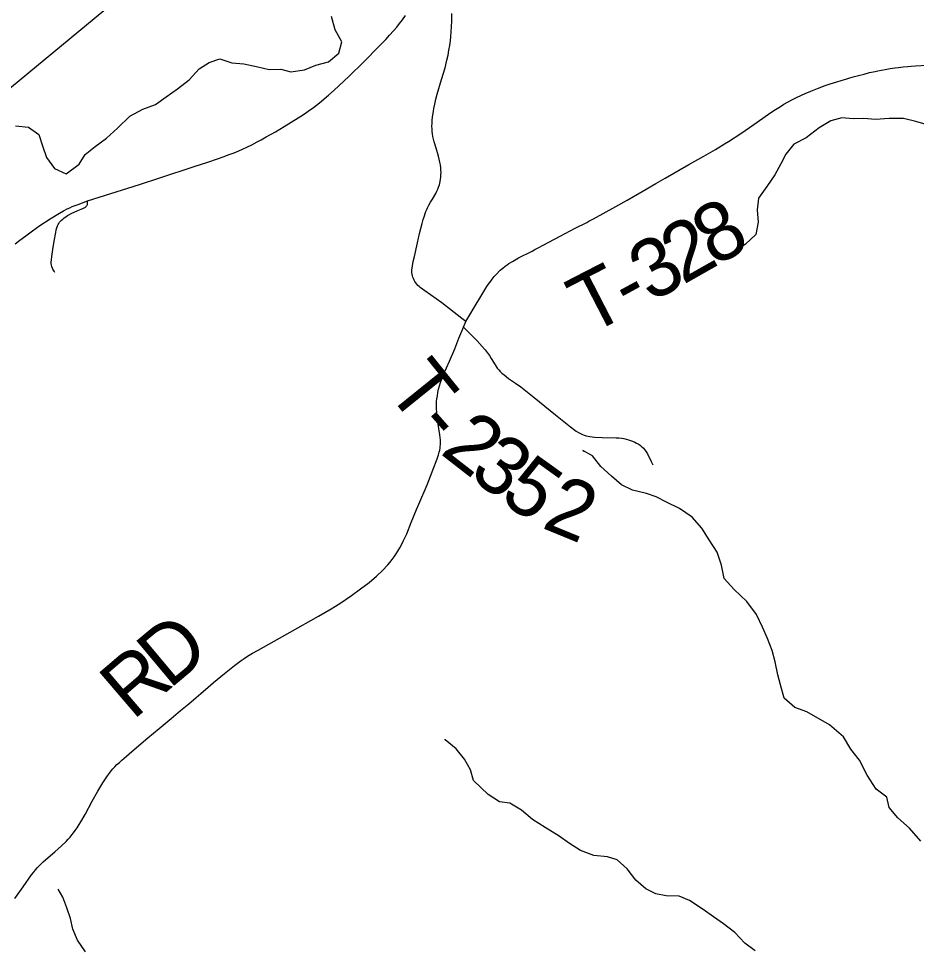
# Model space of a CAD drawing. Extents: x 0 to 34, y 0 to 22.
# Drawn here: x 26.124 to 26.994, y 17.712 to 18.613 of the extents above; entities that cross this region are included whole.
import ezdxf

# ---------------------------------------------------------------- set-up
doc = ezdxf.new("R2010")
doc.units = 0
for name, color, linetype in [('GM_X_Minor_River', 7, 'Continuous'), ('GM_X_Rail_Line', 7, 'Continuous'), ('GM_X_State_Route', 7, 'Continuous'), ('GM_X_Township_Road', 7, 'Continuous'), ('GM_X_Township_Road_Text', 7, 'Continuous')]:
    doc.layers.add(name, color=color, linetype=linetype)

msp = doc.modelspace()

# ---------------------------------------------------------------- linework, layer by layer
at = {"layer": 'GM_X_Minor_River'}
for points in [[(26.1706, 18.46225), (26.18299, 18.47148), (26.18896, 18.48101), (26.19872, 18.48869), (26.20962, 18.49676), (26.22012, 18.50634), (26.23211, 18.51821), (26.24491, 18.52479), (26.25696, 18.52946), (26.26748, 18.53677), (26.27838, 18.54446), (26.28964, 18.55329), (26.29938, 18.564), (26.30915, 18.57017), (26.31933, 18.57368), (26.33108, 18.56964), (26.34243, 18.56862), (26.35606, 18.56573), (26.36705, 18.5632), (26.37838, 18.56369), (26.38823, 18.56115), (26.40145, 18.5628), (26.41237, 18.56746), (26.42444, 18.57062), (26.43458, 18.57906), (26.4375, 18.59008), (26.43098, 18.60175), (26.42746, 18.6146)], [(27.00561, 18.50929), (26.9931, 18.51295), (26.98136, 18.51585), (26.96737, 18.51571), (26.95415, 18.51481), (26.9428, 18.51583), (26.9326, 18.51534), (26.92162, 18.51636), (26.91107, 18.5136), (26.89979, 18.50666), (26.88702, 18.49705), (26.87497, 18.49087), (26.8675, 18.48131), (26.86267, 18.47179), (26.85671, 18.46112), (26.84887, 18.45005), (26.84103, 18.4386), (26.83962, 18.42722), (26.84048, 18.41549), (26.83831, 18.40334), (26.82819, 18.39414), (26.81842, 18.38722), (26.81994, 18.3861)], [(26.12143, 18.50872), (26.13392, 18.50733), (26.14419, 18.50024), (26.14769, 18.48929), (26.15156, 18.47797), (26.15922, 18.46744), (26.1706, 18.46225)], [(26.99804, 17.81589), (26.98697, 17.82828), (26.97591, 17.83839), (26.96751, 17.84853), (26.96516, 17.85836), (26.95488, 17.8662), (26.94607, 17.87975), (26.93876, 17.89445), (26.93035, 17.90497), (26.92306, 17.91701), (26.90973, 17.92862), (26.8877, 17.94127), (26.87595, 17.94531), (26.86566, 17.9543), (26.86215, 17.96714), (26.85979, 17.97697), (26.85704, 17.98944), (26.8543, 18.0004), (26.84966, 18.0121), (26.84465, 18.02303), (26.83887, 18.03547), (26.82969, 18.04788), (26.81749, 18.0595), (26.80757, 18.07038), (26.80519, 18.08323), (26.80092, 18.09569), (26.79326, 18.10773), (26.78598, 18.11902), (26.77681, 18.12954), (26.76426, 18.13812), (26.75174, 18.14405), (26.74186, 18.14925), (26.73238, 18.15256), (26.71875, 18.15582), (26.70812, 18.16102), (26.6986, 18.16925), (26.68831, 18.17862), (26.68028, 18.18914), (26.67078, 18.19434), (26.67193, 18.19322)], [(26.83755, 17.70964), (26.82765, 17.71711), (26.81812, 17.72724), (26.80708, 17.73584), (26.79719, 17.74255), (26.7873, 17.74965), (26.774, 17.75823), (26.76413, 17.76266), (26.75165, 17.76291), (26.74143, 17.7647), (26.73194, 17.76953), (26.72203, 17.77814), (26.71362, 17.78903), (26.7041, 17.79765), (26.69462, 17.80058), (26.68138, 17.80196), (26.66848, 17.80675), (26.65784, 17.81345), (26.64795, 17.82055), (26.63427, 17.82912), (26.62211, 17.83695), (26.61144, 17.84593), (26.60004, 17.85263), (26.5902, 17.85404), (26.57918, 17.86112), (26.56507, 17.87461), (26.56196, 17.88481), (26.5562, 17.89536), (26.54818, 17.90512), (26.53751, 17.91411), (26.53751, 17.91448)], [(26.18926, 17.70852), (26.1816, 17.71981), (26.17697, 17.73075), (26.17461, 17.74095), (26.17112, 17.75114), (26.16725, 17.76171), (26.16265, 17.76924)]]:
    msp.add_lwpolyline(points, dxfattribs=at)
at = {"layer": 'GM_X_Rail_Line'}
msp.add_lwpolyline([(27.31815, 19.07874), (26.87194, 18.96304), (26.63643, 18.90218), (26.59839, 18.89255), (26.55991, 18.88003), (26.5181, 18.86299), (26.49385, 18.84892), (26.46587, 18.83157), (26.32991, 18.7221), (25.62545, 18.13949), (25.57168, 18.09086), (25.53163, 18.0529), (25.48854, 18.00437), (25.44769, 17.95909), (25.41457, 17.91805), (25.38062, 17.87119), (24.86025, 17.12657), (24.35774, 16.41254), (24.32043, 16.36582), (24.27944, 16.32479), (24.2417, 16.29196), (23.98974, 16.09826), (23.66779, 15.84317), (23.51667, 15.72346)], dxfattribs=at)
at = {"layer": 'GM_X_State_Route'}
msp.add_lwpolyline([(26.12118, 18.39433), (26.12578, 18.39802), (26.13137, 18.4023), (26.13786, 18.40715), (26.14516, 18.41221), (26.15503, 18.41862), (26.16407, 18.424), (26.16797, 18.42624), (26.17164, 18.42818), (26.17402, 18.42932), (26.17648, 18.43047), (26.17923, 18.43162), (26.18201, 18.43267), (26.19123, 18.43594), (26.20239, 18.4395), (26.24165, 18.45202), (26.26119, 18.4583), (26.29436, 18.46919), (26.3076, 18.47359), (26.31699, 18.47675), (26.32253, 18.47869), (26.32846, 18.48085), (26.3332, 18.48264), (26.33758, 18.48442), (26.34122, 18.48602), (26.34547, 18.48806), (26.35017, 18.49037), (26.35534, 18.49305), (26.35947, 18.49528), (26.36406, 18.49789), (26.3731, 18.50303), (26.38148, 18.50796), (26.39504, 18.51636), (26.40027, 18.51976), (26.40492, 18.52288), (26.40997, 18.52652), (26.41592, 18.53105), (26.42453, 18.53825), (26.43012, 18.5432), (26.44414, 18.55644), (26.45876, 18.5708), (26.47354, 18.58588), (26.48004, 18.59246), (26.48371, 18.59642), (26.48753, 18.60077), (26.49056, 18.60438), (26.49346, 18.60798), (26.49617, 18.61153), (26.499, 18.6155)], dxfattribs=at)
at = {"layer": 'GM_X_Township_Road'}
msp.add_line((26.55534, 18.3137), (26.55764, 18.31909), dxfattribs=at)
for points in [[(26.55764, 18.31909), (26.5538, 18.32212), (26.53415, 18.3372), (26.51774, 18.34892), (26.51333, 18.35207), (26.51222, 18.35309), (26.51111, 18.35416), (26.51006, 18.35532), (26.50901, 18.35663), (26.50814, 18.35795), (26.50737, 18.35934), (26.5067, 18.36087), (26.50626, 18.36205), (26.50589, 18.36334), (26.50556, 18.36493), (26.50539, 18.36655), (26.50535, 18.36781), (26.50539, 18.36914), (26.50556, 18.37098), (26.50583, 18.37295), (26.50669, 18.37745), (26.50773, 18.38217), (26.51078, 18.39545), (26.51271, 18.40457), (26.51515, 18.41423), (26.5162, 18.41783), (26.51735, 18.42141), (26.51818, 18.42375), (26.51896, 18.42584), (26.5197, 18.42765), (26.5204, 18.42913), (26.52106, 18.43049), (26.52177, 18.43179), (26.52332, 18.43464), (26.52518, 18.43777), (26.52833, 18.44306), (26.52952, 18.44537), (26.53045, 18.44743), (26.53121, 18.44936), (26.53189, 18.45141), (26.53236, 18.4531), (26.53276, 18.45492), (26.5331, 18.45712), (26.53333, 18.45912), (26.53347, 18.46123), (26.53351, 18.46336), (26.53343, 18.46584), (26.53324, 18.46818), (26.53289, 18.47085), (26.53243, 18.47355), (26.53182, 18.47644), (26.53105, 18.47946), (26.52872, 18.48704), (26.52689, 18.49325), (26.52567, 18.49841), (26.52523, 18.501), (26.52496, 18.50336), (26.5248, 18.50591), (26.52477, 18.50834), (26.5248, 18.51109), (26.52498, 18.51394), (26.52529, 18.51733), (26.5258, 18.52071), (26.5262, 18.52305), (26.52664, 18.52555), (26.52752, 18.52982), (26.52857, 18.53468), (26.52981, 18.53942), (26.53395, 18.5536), (26.53736, 18.56474), (26.53929, 18.57245), (26.54031, 18.57728), (26.54121, 18.58204), (26.54193, 18.58642), (26.5426, 18.5911), (26.5431, 18.59537), (26.54346, 18.59966), (26.54376, 18.6049), (26.54393, 18.61001), (26.54409, 18.61764)], [(26.55764, 18.31909), (26.56141, 18.32578), (26.56547, 18.3329), (26.57291, 18.34503), (26.57781, 18.35302), (26.57912, 18.35506), (26.58161, 18.35839), (26.58304, 18.36019), (26.58509, 18.36261), (26.587, 18.36484), (26.59087, 18.36875), (26.59335, 18.37091), (26.59553, 18.37268), (26.5975, 18.37412), (26.59906, 18.37527), (26.60256, 18.37746), (26.60848, 18.38069), (26.62166, 18.38739), (26.62438, 18.3888), (26.62765, 18.39046), (26.63246, 18.39296), (26.64872, 18.40171), (26.66351, 18.40956), (26.67456, 18.41521), (26.67675, 18.41635), (26.68114, 18.41861), (26.70282, 18.43066), (26.71359, 18.43675), (26.72813, 18.44499), (26.74156, 18.45274), (26.75067, 18.45802), (26.77344, 18.47125), (26.78788, 18.47934), (26.79913, 18.48578), (26.80815, 18.4912), (26.81185, 18.49349), (26.82378, 18.50126), (26.83649, 18.5101), (26.85068, 18.52007), (26.85591, 18.52365), (26.86207, 18.52751), (26.86548, 18.52965), (26.8695, 18.53194), (26.87386, 18.53429), (26.87772, 18.53623), (26.88241, 18.53844), (26.88614, 18.5401), (26.8917, 18.54243), (26.89817, 18.54501), (26.90547, 18.54769), (26.91044, 18.54931), (26.9167, 18.55139), (26.92107, 18.5527), (26.92549, 18.55406), (26.92938, 18.55516), (26.93375, 18.55636), (26.93774, 18.55743), (26.94313, 18.55884), (26.9485, 18.56023), (26.95391, 18.56139), (26.95632, 18.56197), (26.95989, 18.56273), (26.96358, 18.56343), (26.96848, 18.56421), (26.97292, 18.56487), (26.97639, 18.56527), (26.9811, 18.56581), (26.98563, 18.56618), (26.98871, 18.56642), (26.99304, 18.56675), (27.00415, 18.56762)], [(26.15969, 18.36654), (26.15879, 18.36809), (26.15777, 18.36998), (26.15707, 18.37143), (26.15666, 18.37252), (26.15635, 18.37375), (26.15615, 18.37521), (26.15615, 18.3768), (26.15629, 18.37877), (26.15664, 18.38205), (26.15768, 18.38904), (26.15897, 18.39684), (26.16046, 18.40541), (26.161, 18.40798), (26.1615, 18.4098), (26.16186, 18.41094), (26.16227, 18.41197), (26.16278, 18.41304), (26.16351, 18.41422), (26.16424, 18.41526), (26.16507, 18.4163), (26.16601, 18.41731), (26.16725, 18.41842), (26.16856, 18.41953), (26.17018, 18.42069), (26.17193, 18.42179), (26.17387, 18.42295), (26.17595, 18.42405), (26.1783, 18.42513), (26.18188, 18.42668), (26.18521, 18.42804), (26.18738, 18.4289), (26.18854, 18.42948), (26.18923, 18.42997), (26.18987, 18.43052), (26.19034, 18.43112), (26.19075, 18.43173), (26.19104, 18.43247), (26.1912, 18.43318), (26.19129, 18.43387), (26.19129, 18.43461), (26.19123, 18.43594)], [(26.12086, 17.76016), (26.12892, 17.7716), (26.13708, 17.78318), (26.13886, 17.78564), (26.14076, 17.78795), (26.1427, 17.79022), (26.14471, 17.7923), (26.1483, 17.79579), (26.15302, 17.79987), (26.15966, 17.80546), (26.16607, 17.81127), (26.17043, 17.81559), (26.17248, 17.81782), (26.17428, 17.81981), (26.17604, 17.82194), (26.1776, 17.82394), (26.17927, 17.82619), (26.18117, 17.82889), (26.18311, 17.83193), (26.18475, 17.83459), (26.18882, 17.84169), (26.19565, 17.85455), (26.20109, 17.86434), (26.20593, 17.87235), (26.21045, 17.87911), (26.2124, 17.88177), (26.21405, 17.88391), (26.2158, 17.88589), (26.2177, 17.88797), (26.21972, 17.88995), (26.22215, 17.89214), (26.22447, 17.89421), (26.22912, 17.89828), (26.2342, 17.90263), (26.24968, 17.91595), (26.26066, 17.92508), (26.27207, 17.9345), (26.28141, 17.94239), (26.28933, 17.949), (26.29628, 17.95494), (26.30101, 17.95889), (26.30802, 17.96497), (26.31317, 17.96945), (26.32371, 17.97819), (26.33347, 17.98593), (26.33998, 17.99075), (26.34288, 17.99278), (26.34619, 17.99495), (26.35111, 17.99788), (26.35637, 18.00099), (26.38731, 18.01815), (26.4149, 18.03371), (26.42714, 18.04087), (26.43547, 18.04614), (26.44667, 18.05367), (26.45569, 18.0601), (26.46403, 18.06646), (26.47109, 18.07243), (26.47692, 18.07794), (26.48195, 18.08336), (26.48401, 18.08582), (26.4862, 18.08862), (26.48804, 18.09124), (26.49005, 18.09416), (26.49166, 18.09683), (26.49351, 18.09994), (26.4952, 18.10299), (26.49716, 18.10698), (26.50025, 18.11365), (26.50476, 18.12447), (26.50991, 18.13709), (26.5121, 18.14219), (26.52006, 18.16093), (26.52664, 18.17761), (26.52885, 18.18357), (26.53015, 18.18723), (26.53109, 18.19006), (26.53179, 18.19253), (26.53225, 18.19451), (26.53258, 18.1964), (26.53278, 18.19808), (26.53291, 18.20006), (26.53294, 18.20199), (26.53286, 18.20421), (26.53266, 18.20688), (26.53232, 18.20956), (26.53036, 18.22176), (26.52947, 18.22981), (26.52919, 18.23606), (26.52918, 18.23884), (26.52926, 18.24155), (26.52951, 18.24434), (26.52994, 18.24734), (26.53041, 18.25026), (26.53118, 18.2535), (26.53212, 18.25694), (26.53311, 18.26013), (26.53434, 18.26363), (26.53595, 18.26775), (26.54165, 18.28089), (26.5468, 18.29284), (26.55084, 18.30319), (26.55367, 18.3098), (26.55534, 18.3137)], [(26.55534, 18.3137), (26.55774, 18.31119), (26.56196, 18.30681), (26.56845, 18.30044), (26.57333, 18.29506), (26.57613, 18.29167), (26.57907, 18.28801), (26.58045, 18.2862), (26.58217, 18.28349), (26.58593, 18.27714), (26.58685, 18.27565), (26.58802, 18.27408), (26.5895, 18.27235), (26.59089, 18.27083), (26.59253, 18.26928), (26.59454, 18.26748), (26.59895, 18.26403), (26.60564, 18.2595), (26.61067, 18.25586), (26.62376, 18.24542), (26.64447, 18.22863), (26.65897, 18.21702), (26.66295, 18.21406), (26.66446, 18.21301), (26.66664, 18.21178), (26.67053, 18.20987), (26.67226, 18.20918), (26.67403, 18.2086), (26.67765, 18.20776), (26.67999, 18.20741), (26.68258, 18.20711), (26.68939, 18.20678), (26.70302, 18.20653), (26.70579, 18.20636), (26.70859, 18.20609), (26.71049, 18.20577), (26.71286, 18.20525), (26.71488, 18.20466), (26.71702, 18.204), (26.71906, 18.20319), (26.72102, 18.20233), (26.72268, 18.20149), (26.72428, 18.20056), (26.72626, 18.19926), (26.72733, 18.19845), (26.72962, 18.19638), (26.73069, 18.19518), (26.7316, 18.19403), (26.73353, 18.19089), (26.73707, 18.18368), (26.7387, 18.18036)]]:
    msp.add_lwpolyline(points, dxfattribs=at)

# ---------------------------------------------------------------- texts
at = {"layer": 'GM_X_Township_Road_Text'}
for s, rotation, p in [('8', 29.62969, (26.79827, 18.37172)), ('2', 29.50855, (26.76769, 18.35442)), ('3', 29.05303, (26.73667, 18.33718)), ('T', 27.28956, (26.67672, 18.30563)), ('-', 28.56893, (26.71572, 18.32577)), ('T', 308.88203, (26.47928, 18.25251)), ('-', 311.21779, (26.50758, 18.2175)), ('2', 322.12676, (26.53153, 18.19187)), ('3', 321.87171, (26.55911, 18.17042)), ('5', 324.34205, (26.58877, 18.14721)), ('2', 337.66829, (26.62979, 18.11984)), ('D', 39.94362, (26.27028, 17.96237)), ('R', 40.52869, (26.23493, 17.93215))]:
    msp.add_text(s, height=0.05682, rotation=rotation, dxfattribs=at).set_placement(p)

doc.saveas('drawing.dxf')
